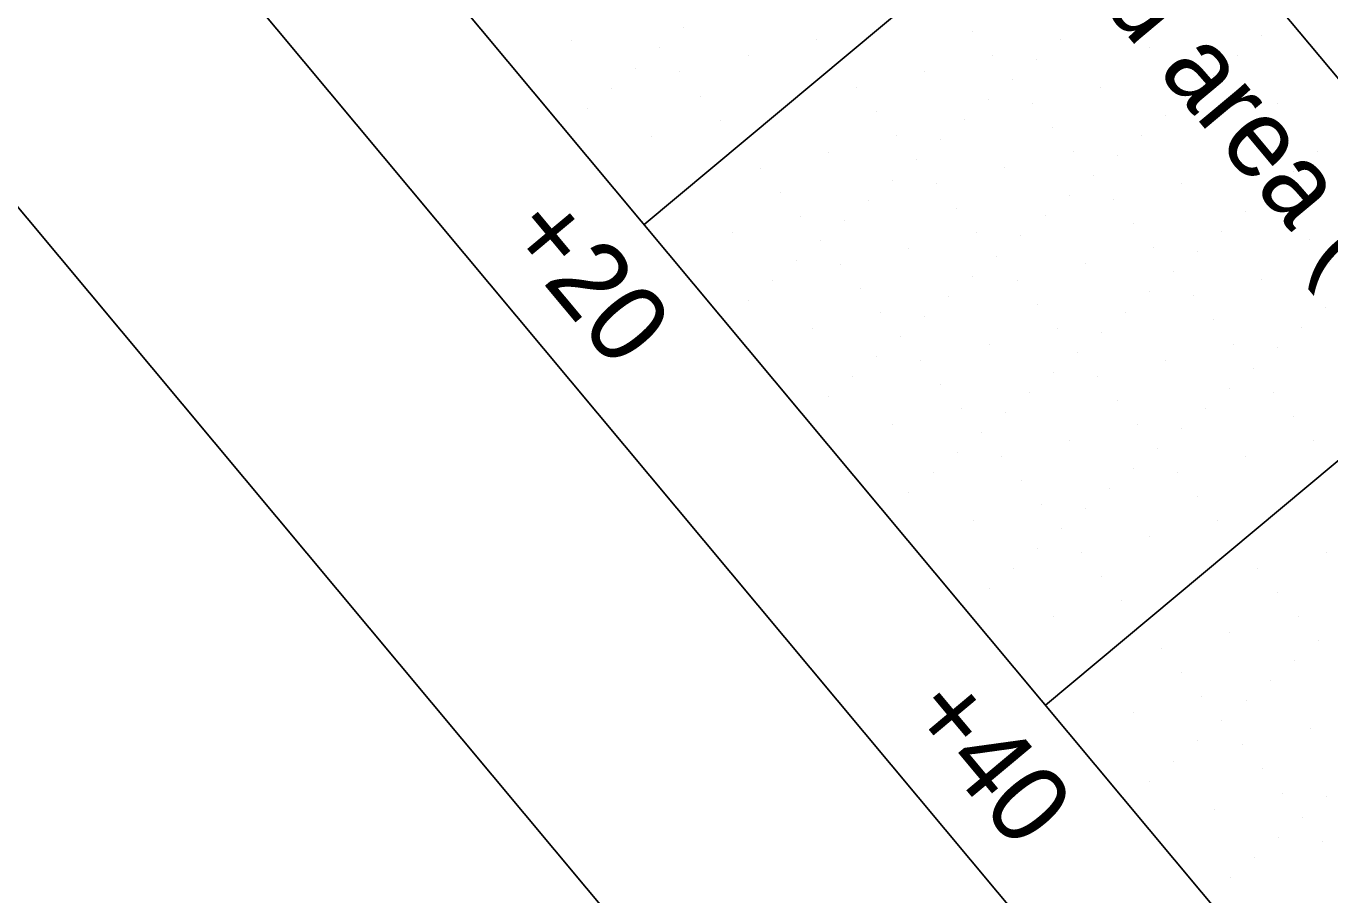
# Model space of a CAD drawing. Extents: x 2042995 to 2043795, y 305365 to 306249.
# Drawn here: x 2043226.41 to 2043268.05, y 305668.61 to 305696.35 of the extents above; entities that cross this region are included whole.
import ezdxf

# ---------------------------------------------------------------- set-up
doc = ezdxf.new("R2010")
doc.units = 0
for name, color, linetype in [('BR_AUTO DIMENSION', 7, 'Continuous'), ('BR_BORDER LINES', 7, 'Continuous'), ('BR_CONCRETE', 7, 'Continuous'), ('BR_GRID DOTS', 7, 'Continuous'), ('BR_GRID LINES', 7, 'Continuous'), ('BR_TEXT', 7, 'Continuous'), ('RD_SHT_IplotShp', 7, 'Continuous')]:
    doc.layers.add(name, color=color, linetype=linetype)

msp = doc.modelspace()

# ---------------------------------------------------------------- linework, layer by layer
at = {"layer": 'BR_BORDER LINES'}
for p, q in [((2043026.498, 305945.211), (2043458.121, 305428.416)), ((2043041.019, 305935.624), (2043355.122, 305559.54))]:
    msp.add_line(p, q, dxfattribs=at)
at = {"layer": 'BR_CONCRETE'}
msp.add_spline([(2043139.109, 306017.548), (2043148.199, 306007.16), (2043160.233, 305993.368), (2043172.245, 305979.557), (2043184.234, 305965.727), (2043196.201, 305951.879), (2043208.145, 305938.012), (2043220.067, 305924.126), (2043231.966, 305910.221), (2043243.843, 305896.297), (2043255.698, 305882.355), (2043267.529, 305868.394), (2043279.339, 305854.414), (2043291.126, 305840.415), (2043302.89, 305826.398), (2043314.632, 305812.361), (2043326.352, 305798.306), (2043338.049, 305784.233), (2043349.724, 305770.14), (2043361.376, 305756.029), (2043373.005, 305741.899), (2043384.613, 305727.75), (2043396.197, 305713.582), (2043407.76, 305699.396), (2043419.299, 305685.191), (2043430.817, 305670.967), (2043442.311, 305656.724), (2043453.784, 305642.463), (2043465.234, 305628.182), (2043476.661, 305613.883), (2043488.066, 305599.566), (2043499.448, 305585.229), (2043510.808, 305570.874), (2043522.146, 305556.5), (2043533.461, 305542.107), (2043544.753, 305527.695), (2043547.219, 305524.543)], degree=3, dxfattribs=at)
at = {"layer": 'BR_GRID DOTS'}
for p, q in [((2043247.421, 305696.293), (2043247.421, 305696.293)), ((2043256.64, 305696.175), (2043256.64, 305696.175)), ((2043243.836, 305695.905), (2043243.836, 305695.905)), ((2043251.646, 305695.914), (2043251.646, 305695.914)), ((2043259.457, 305695.922), (2043259.457, 305695.922)), ((2043265.858, 305696.057), (2043265.858, 305696.057)), ((2043246.653, 305695.652), (2043246.653, 305695.652)), ((2043249.47, 305695.399), (2043249.47, 305695.399)), ((2043257.281, 305695.408), (2043257.281, 305695.408)), ((2043262.274, 305695.669), (2043262.274, 305695.669)), ((2043265.091, 305695.416), (2043265.091, 305695.416)), ((2043245.886, 305695.011), (2043245.886, 305695.011)), ((2043247.294, 305694.885), (2043247.294, 305694.885)), ((2043255.105, 305694.893), (2043255.105, 305694.893)), ((2043258.689, 305695.281), (2043258.689, 305695.281)), ((2043262.915, 305694.902), (2043262.915, 305694.902)), ((2043257.922, 305694.64), (2043257.922, 305694.64)), ((2043264.323, 305694.775), (2043264.323, 305694.775)), ((2043245.118, 305694.37), (2043245.118, 305694.37)), ((2043247.935, 305694.117), (2043247.935, 305694.117)), ((2043252.929, 305694.379), (2043252.929, 305694.379)), ((2043260.739, 305694.387), (2043260.739, 305694.387)), ((2043263.556, 305694.134), (2043263.556, 305694.134)), ((2043244.351, 305693.729), (2043244.351, 305693.729)), ((2043257.154, 305693.999), (2043257.154, 305693.999)), ((2043258.563, 305693.873), (2043258.563, 305693.873)), ((2043266.373, 305693.881), (2043266.373, 305693.881)), ((2043248.576, 305693.35), (2043248.576, 305693.35)), ((2043253.57, 305693.611), (2043253.57, 305693.611)), ((2043256.387, 305693.358), (2043256.387, 305693.358)), ((2043262.788, 305693.493), (2043262.788, 305693.493)), ((2043264.197, 305693.367), (2043264.197, 305693.367)), ((2043246.4, 305692.835), (2043246.4, 305692.835)), ((2043254.211, 305692.844), (2043254.211, 305692.844)), ((2043259.204, 305693.105), (2043259.204, 305693.105)), ((2043262.021, 305692.852), (2043262.021, 305692.852)), ((2043255.619, 305692.717), (2043255.619, 305692.717)), ((2043264.838, 305692.599), (2043264.838, 305692.599)), ((2043252.034, 305692.329), (2043252.034, 305692.329)), ((2043254.852, 305692.076), (2043254.852, 305692.076)), ((2043259.845, 305692.338), (2043259.845, 305692.338)), ((2043261.253, 305692.211), (2043261.253, 305692.211)), ((2043267.655, 305692.346), (2043267.655, 305692.346)), ((2043249.858, 305691.815), (2043249.858, 305691.815)), ((2043257.669, 305691.823), (2043257.669, 305691.823)), ((2043260.486, 305691.57), (2043260.486, 305691.57)), ((2043265.479, 305691.832), (2043265.479, 305691.832)), ((2043266.887, 305691.705), (2043266.887, 305691.705)), ((2043254.084, 305691.435), (2043254.084, 305691.435)), ((2043255.493, 305691.309), (2043255.493, 305691.309)), ((2043263.303, 305691.317), (2043263.303, 305691.317)), ((2043250.499, 305691.047), (2043250.499, 305691.047)), ((2043253.317, 305690.794), (2043253.317, 305690.794)), ((2043259.718, 305690.929), (2043259.718, 305690.929)), ((2043261.127, 305690.803), (2043261.127, 305690.803)), ((2043266.12, 305691.064), (2043266.12, 305691.064)), ((2043256.134, 305690.541), (2043256.134, 305690.541)), ((2043265.352, 305690.423), (2043265.352, 305690.423)), ((2043266.761, 305690.297), (2043266.761, 305690.297)), ((2043251.14, 305690.28), (2043251.14, 305690.28)), ((2043252.549, 305690.153), (2043252.549, 305690.153)), ((2043258.951, 305690.288), (2043258.951, 305690.288)), ((2043261.768, 305690.035), (2043261.768, 305690.035)), ((2043248.964, 305689.765), (2043248.964, 305689.765)), ((2043251.782, 305689.512), (2043251.782, 305689.512)), ((2043256.775, 305689.774), (2043256.775, 305689.774)), ((2043258.183, 305689.647), (2043258.183, 305689.647)), ((2043264.585, 305689.782), (2043264.585, 305689.782)), ((2043267.402, 305689.529), (2043267.402, 305689.529)), ((2043254.599, 305689.259), (2043254.599, 305689.259)), ((2043262.409, 305689.268), (2043262.409, 305689.268)), ((2043263.817, 305689.141), (2043263.817, 305689.141)), ((2043251.014, 305688.871), (2043251.014, 305688.871)), ((2043252.423, 305688.745), (2043252.423, 305688.745)), ((2043257.416, 305689.006), (2043257.416, 305689.006)), ((2043260.233, 305688.753), (2043260.233, 305688.753)), ((2043268.043, 305688.762), (2043268.043, 305688.762)), ((2043250.246, 305688.23), (2043250.246, 305688.23)), ((2043256.648, 305688.365), (2043256.648, 305688.365)), ((2043258.057, 305688.239), (2043258.057, 305688.239)), ((2043263.05, 305688.5), (2043263.05, 305688.5)), ((2043265.867, 305688.247), (2043265.867, 305688.247)), ((2043253.064, 305687.977), (2043253.064, 305687.977)), ((2043262.282, 305687.859), (2043262.282, 305687.859)), ((2043249.479, 305687.589), (2043249.479, 305687.589)), ((2043255.881, 305687.724), (2043255.881, 305687.724)), ((2043258.698, 305687.471), (2043258.698, 305687.471)), ((2043263.691, 305687.733), (2043263.691, 305687.733)), ((2043253.705, 305687.21), (2043253.705, 305687.21)), ((2043255.113, 305687.083), (2043255.113, 305687.083)), ((2043261.515, 305687.218), (2043261.515, 305687.218)), ((2043264.332, 305686.965), (2043264.332, 305686.965)), ((2043267.917, 305687.353), (2043267.917, 305687.353)), ((2043251.529, 305686.695), (2043251.529, 305686.695)), ((2043259.339, 305686.704), (2043259.339, 305686.704)), ((2043260.747, 305686.577), (2043260.747, 305686.577)), ((2043267.149, 305686.712), (2043267.149, 305686.712)), ((2043254.346, 305686.442), (2043254.346, 305686.442)), ((2043257.163, 305686.189), (2043257.163, 305686.189)), ((2043264.973, 305686.198), (2043264.973, 305686.198)), ((2043253.578, 305685.801), (2043253.578, 305685.801)), ((2043259.98, 305685.936), (2043259.98, 305685.936)), ((2043266.381, 305686.071), (2043266.381, 305686.071)), ((2043254.987, 305685.675), (2043254.987, 305685.675)), ((2043262.797, 305685.683), (2043262.797, 305685.683)), ((2043265.614, 305685.43), (2043265.614, 305685.43)), ((2043252.811, 305685.16), (2043252.811, 305685.16)), ((2043255.628, 305684.907), (2043255.628, 305684.907)), ((2043259.212, 305685.295), (2043259.212, 305685.295)), ((2043260.621, 305685.169), (2043260.621, 305685.169)), ((2043252.043, 305684.519), (2043252.043, 305684.519)), ((2043258.445, 305684.654), (2043258.445, 305684.654)), ((2043264.846, 305684.789), (2043264.846, 305684.789)), ((2043266.255, 305684.663), (2043266.255, 305684.663)), ((2043256.269, 305684.139), (2043256.269, 305684.139)), ((2043261.262, 305684.401), (2043261.262, 305684.401)), ((2043264.079, 305684.148), (2043264.079, 305684.148)), ((2043257.677, 305684.013), (2043257.677, 305684.013)), ((2043261.903, 305683.634), (2043261.903, 305683.634)), ((2043266.896, 305683.895), (2043266.896, 305683.895)), ((2043254.093, 305683.625), (2043254.093, 305683.625)), ((2043256.91, 305683.372), (2043256.91, 305683.372)), ((2043263.311, 305683.507), (2043263.311, 305683.507)), ((2043259.727, 305683.119), (2043259.727, 305683.119)), ((2043262.544, 305682.866), (2043262.544, 305682.866)), ((2043267.537, 305683.128), (2043267.537, 305683.128)), ((2043256.142, 305682.731), (2043256.142, 305682.731)), ((2043257.551, 305682.604), (2043257.551, 305682.604)), ((2043265.361, 305682.613), (2043265.361, 305682.613)), ((2043255.375, 305682.09), (2043255.375, 305682.09)), ((2043261.776, 305682.225), (2043261.776, 305682.225)), ((2043263.185, 305682.098), (2043263.185, 305682.098)), ((2043258.192, 305681.837), (2043258.192, 305681.837)), ((2043261.009, 305681.584), (2043261.009, 305681.584)), ((2043254.607, 305681.449), (2043254.607, 305681.449)), ((2043263.826, 305681.331), (2043263.826, 305681.331)), ((2043258.833, 305681.069), (2043258.833, 305681.069)), ((2043260.241, 305680.943), (2043260.241, 305680.943)), ((2043256.657, 305680.555), (2043256.657, 305680.555)), ((2043259.474, 305680.302), (2043259.474, 305680.302)), ((2043264.467, 305680.563), (2043264.467, 305680.563)), ((2043262.291, 305680.049), (2043262.291, 305680.049)), ((2043258.706, 305679.661), (2043258.706, 305679.661)), ((2043260.115, 305679.534), (2043260.115, 305679.534)), ((2043267.925, 305679.543), (2043267.925, 305679.543)), ((2043257.939, 305679.02), (2043257.939, 305679.02)), ((2043260.756, 305678.767), (2043260.756, 305678.767)), ((2043265.749, 305679.028), (2043265.749, 305679.028)), ((2043257.171, 305678.379), (2043257.171, 305678.379)), ((2043266.39, 305678.261), (2043266.39, 305678.261)), ((2043261.397, 305677.999), (2043261.397, 305677.999)), ((2043259.221, 305677.485), (2043259.221, 305677.485)), ((2043267.031, 305677.493), (2043267.031, 305677.493)), ((2043264.855, 305676.979), (2043264.855, 305676.979)), ((2043267.672, 305676.726), (2043267.672, 305676.726)), ((2043262.679, 305676.464), (2043262.679, 305676.464)), ((2043266.905, 305676.085), (2043266.905, 305676.085)), ((2043263.32, 305675.697), (2043263.32, 305675.697)), ((2043266.137, 305675.444), (2043266.137, 305675.444)), ((2043263.961, 305674.929), (2043263.961, 305674.929)), ((2043265.37, 305674.803), (2043265.37, 305674.803)), ((2043261.785, 305674.415), (2043261.785, 305674.415)), ((2043264.602, 305674.162), (2043264.602, 305674.162)), ((2043267.419, 305673.909), (2043267.419, 305673.909)), ((2043263.835, 305673.521), (2043263.835, 305673.521)), ((2043265.243, 305673.394), (2043265.243, 305673.394)), ((2043263.067, 305672.88), (2043263.067, 305672.88)), ((2043265.884, 305672.627), (2043265.884, 305672.627)), ((2043262.299, 305672.239), (2043262.299, 305672.239)), ((2043266.525, 305671.859), (2043266.525, 305671.859)), ((2043267.934, 305671.733), (2043267.934, 305671.733)), ((2043264.349, 305671.345), (2043264.349, 305671.345)), ((2043267.166, 305671.092), (2043267.166, 305671.092)), ((2043266.399, 305670.451), (2043266.399, 305670.451)), ((2043267.807, 305670.324), (2043267.807, 305670.324)), ((2043265.631, 305669.81), (2043265.631, 305669.81)), ((2043264.864, 305669.169), (2043264.864, 305669.169))]:
    msp.add_line(p, q, dxfattribs=at)
at = {"layer": 'BR_GRID LINES'}
for p, q in [((2043133.293, 305856.342), (2043340.985, 305607.666)), ((2043399.651, 305818.223), (2043246.147, 305690.018)), ((2043412.472, 305802.873), (2043258.968, 305674.668))]:
    msp.add_line(p, q, dxfattribs=at)
at = {"layer": 'RD_SHT_IplotShp'}
msp.add_lwpolyline([(2043333.027, 306248.995), (2043794.566, 305696.382), (2043456.858, 305414.33), (2042995.319, 305966.944)], close=True, dxfattribs=at)

# ---------------------------------------------------------------- texts
at = {"layer": 'BR_AUTO DIMENSION'}
msp.add_text('= Excavate hatched area (See Road Plans)', height=2.5, rotation=309.8684, dxfattribs=at).set_placement((2043243.051, 305718.224))
at = {"layer": 'BR_TEXT'}
for s, height, p in [('SECTION ALONG L US 17A  US 21', 8.12508, (2043221.449, 305763.122)), ('+20', 2.5, (2043241.622, 305689.686)), ('+40', 2.5, (2043254.443, 305674.335))]:
    msp.add_text(s, height=height, rotation=309.8684, dxfattribs=at).set_placement(p)

doc.saveas('drawing.dxf')
